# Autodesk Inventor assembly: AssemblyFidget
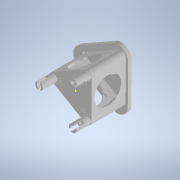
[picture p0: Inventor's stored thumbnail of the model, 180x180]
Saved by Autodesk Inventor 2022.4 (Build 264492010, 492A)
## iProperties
Created: 2023-09
Part Number: AssemblyFidget
Document SubType Name: Assembly
Designer: tmass
Author: tmass
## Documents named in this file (5)
- C:\Users\tmass\OneDrive\Bureau\UFO paper\3D models\Fidget\Inventor\AssemblyFidget.iam
- C:\Users\tmass\OneDrive\Bureau\UFO paper\3D models\Fidget\Inventor\Reactor small aircooled.ipt
- C:\Users\tmass\OneDrive\Bureau\UFO paper\3D models\Fidget\Inventor\Lid small.ipt
- C:\Users\tmass\OneDrive\Bureau\UFO paper\3D models\Fidget\Inventor\mini fidget foot.ipt
- C:\Users\tmass\OneDrive\Bureau\UFO paper\3D models\Fidget\Inventor\Coil holder.ipt
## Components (6 placed, 4 different names)
1. Reactor small aircooled:1 — Mate:1, Mate:2, Mate:3, Mate:4, Mate:5, Mate:6, Mate:7, Mate:8, Mate:9, Mate:10, Mate:11, Mate:12
2. Lid small:1 — Mate:4, Mate:5, Mate:6
3. mini fidget foot:1 — Mate:8, Mate:10
4. mini fidget foot:2 — Mate:7, Mate:11
5. mini fidget foot:3 — Mate:9, Mate:12
6. Coil holder:1 — Mate:1, Mate:2, Mate:3
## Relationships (12: Mate 12)
- Mate:1: Reactor small aircooled:1 ↔ Coil holder:1
- Mate:2: Reactor small aircooled:1 ↔ Coil holder:1
- Mate:3: Reactor small aircooled:1 ↔ Coil holder:1
- Mate:4: Reactor small aircooled:1 ↔ Lid small:1
- Mate:5: Reactor small aircooled:1 ↔ Lid small:1
- Mate:6: Reactor small aircooled:1 ↔ Lid small:1
- Mate:7: Reactor small aircooled:1 ↔ mini fidget foot:2
- Mate:8: Reactor small aircooled:1 ↔ mini fidget foot:1
- Mate:9: Reactor small aircooled:1 ↔ mini fidget foot:3
- Mate:10: Reactor small aircooled:1 ↔ mini fidget foot:1
- Mate:11: Reactor small aircooled:1 ↔ mini fidget foot:2
- Mate:12: Reactor small aircooled:1 ↔ mini fidget foot:3
